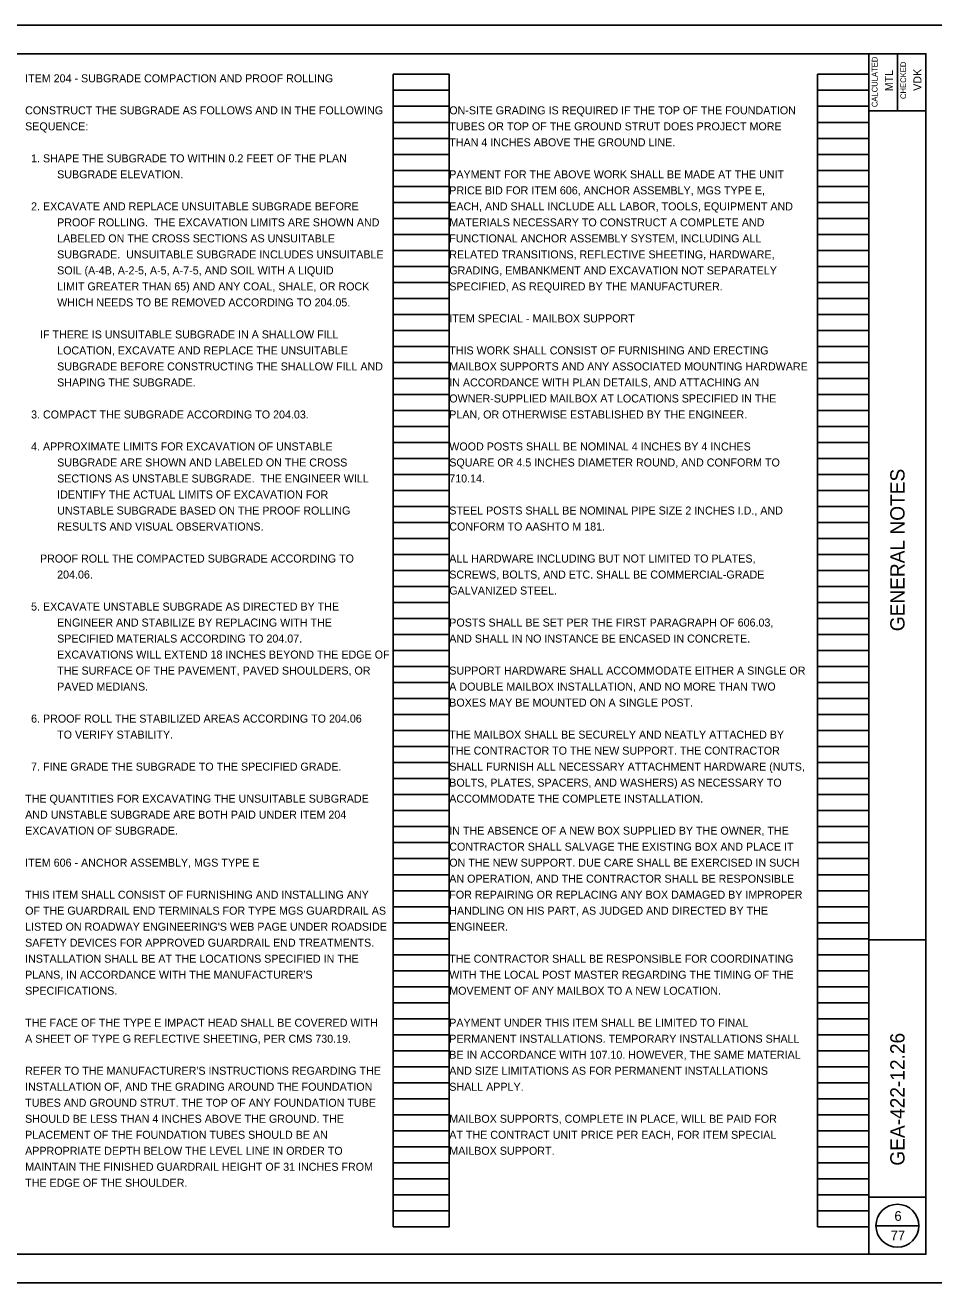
# Model space of a CAD drawing. Extents: x 0 to 41.8, y 0 to 22.
# Drawn here: x 17.74 to 33.64, y 0 to 22 of the extents above; entities that cross this region are included whole.
import ezdxf

# ---------------------------------------------------------------- set-up
doc = ezdxf.new("R2010")
doc.units = 0
for name, color, linetype in [('SC_Scratch1', 7, 'Continuous'), ('SH_Border', 7, 'Continuous'), ('SH_Cut_Line', 7, 'Continuous'), ('SH_Data', 7, 'Continuous'), ('SH_Text', 7, 'Continuous')]:
    doc.layers.add(name, color=color, linetype=linetype)

msp = doc.modelspace()

# ---------------------------------------------------------------- linework, layer by layer
at = {"layer": 'SC_Scratch1'}
for p, q in [((24.18, 0.98), (24.18, 21.14)), ((24.18, 21.14), (25.16, 21.14)), ((25.16, 0.98), (25.16, 21.14)), ((31.6, 0.98), (31.6, 21.14)), ((31.6, 21.14), (32.5, 21.14)), ((32.5, 0.98), (32.5, 21.14)), ((24.18, 20.86), (25.16, 20.86)), ((31.6, 20.86), (32.5, 20.86)), ((24.18, 20.58), (25.16, 20.58)), ((31.6, 20.58), (32.5, 20.58)), ((24.18, 20.3), (25.16, 20.3)), ((31.6, 20.3), (32.5, 20.3)), ((24.18, 20.02), (25.16, 20.02)), ((31.6, 20.02), (32.5, 20.02)), ((24.18, 19.74), (25.16, 19.74)), ((31.6, 19.74), (32.5, 19.74)), ((24.18, 19.46), (25.16, 19.46)), ((31.6, 19.46), (32.5, 19.46)), ((24.18, 19.18), (25.16, 19.18)), ((31.6, 19.18), (32.5, 19.18)), ((24.18, 18.9), (25.16, 18.9)), ((31.6, 18.9), (32.5, 18.9)), ((24.18, 18.62), (25.16, 18.62)), ((31.6, 18.62), (32.5, 18.62)), ((24.18, 18.34), (25.16, 18.34)), ((31.6, 18.34), (32.5, 18.34)), ((24.18, 18.06), (25.16, 18.06)), ((31.6, 18.06), (32.5, 18.06)), ((24.18, 17.78), (25.16, 17.78)), ((31.6, 17.78), (32.5, 17.78)), ((24.18, 17.5), (25.16, 17.5)), ((31.6, 17.5), (32.5, 17.5)), ((24.18, 17.22), (25.16, 17.22)), ((31.6, 17.22), (32.5, 17.22)), ((24.18, 16.94), (25.16, 16.94)), ((31.6, 16.94), (32.5, 16.94)), ((24.18, 16.66), (25.16, 16.66)), ((31.6, 16.66), (32.5, 16.66)), ((24.18, 16.38), (25.16, 16.38)), ((31.6, 16.38), (32.5, 16.38)), ((24.18, 16.1), (25.16, 16.1)), ((31.6, 16.1), (32.5, 16.1)), ((24.18, 15.82), (25.16, 15.82)), ((31.6, 15.82), (32.5, 15.82)), ((24.18, 15.54), (25.16, 15.54)), ((31.6, 15.54), (32.5, 15.54)), ((24.18, 15.26), (25.16, 15.26)), ((31.6, 15.26), (32.5, 15.26)), ((24.18, 14.98), (25.16, 14.98)), ((31.6, 14.98), (32.5, 14.98)), ((24.18, 14.7), (25.16, 14.7)), ((31.6, 14.7), (32.5, 14.7)), ((24.18, 14.42), (25.16, 14.42)), ((31.6, 14.42), (32.5, 14.42)), ((24.18, 14.14), (25.16, 14.14)), ((31.6, 14.14), (32.5, 14.14)), ((24.18, 13.86), (25.16, 13.86)), ((31.6, 13.86), (32.5, 13.86)), ((24.18, 13.58), (25.16, 13.58)), ((31.6, 13.58), (32.5, 13.58)), ((24.18, 13.3), (25.16, 13.3)), ((31.6, 13.3), (32.5, 13.3)), ((24.18, 13.02), (25.16, 13.02)), ((31.6, 13.02), (32.5, 13.02)), ((24.18, 12.74), (25.16, 12.74)), ((31.6, 12.74), (32.5, 12.74)), ((24.18, 12.46), (25.16, 12.46)), ((31.6, 12.46), (32.5, 12.46)), ((24.18, 12.18), (25.16, 12.18)), ((31.6, 12.18), (32.5, 12.18)), ((24.18, 11.9), (25.16, 11.9)), ((31.6, 11.9), (32.5, 11.9)), ((24.18, 11.62), (25.16, 11.62)), ((31.6, 11.62), (32.5, 11.62)), ((24.18, 11.34), (25.16, 11.34)), ((31.6, 11.34), (32.5, 11.34)), ((24.18, 11.06), (25.16, 11.06)), ((31.6, 11.06), (32.5, 11.06)), ((24.18, 10.78), (25.16, 10.78)), ((31.6, 10.78), (32.5, 10.78)), ((24.18, 10.5), (25.16, 10.5)), ((31.6, 10.5), (32.5, 10.5)), ((24.18, 10.22), (25.16, 10.22)), ((31.6, 10.22), (32.5, 10.22)), ((24.18, 9.94), (25.16, 9.94)), ((31.6, 9.94), (32.5, 9.94)), ((24.18, 9.66), (25.16, 9.66)), ((31.6, 9.66), (32.5, 9.66)), ((24.18, 9.38), (25.16, 9.38)), ((31.6, 9.38), (32.5, 9.38)), ((24.18, 9.1), (25.16, 9.1)), ((31.6, 9.1), (32.5, 9.1)), ((24.18, 8.82), (25.16, 8.82)), ((31.6, 8.82), (32.5, 8.82)), ((24.18, 8.54), (25.16, 8.54)), ((31.6, 8.54), (32.5, 8.54)), ((24.18, 8.26), (25.16, 8.26)), ((31.6, 8.26), (32.5, 8.26)), ((24.18, 7.98), (25.16, 7.98)), ((31.6, 7.98), (32.5, 7.98)), ((24.18, 7.7), (25.16, 7.7)), ((31.6, 7.7), (32.5, 7.7)), ((24.18, 7.42), (25.16, 7.42)), ((31.6, 7.42), (32.5, 7.42)), ((24.18, 7.14), (25.16, 7.14)), ((31.6, 7.14), (32.5, 7.14)), ((24.18, 6.86), (25.16, 6.86)), ((31.6, 6.86), (32.5, 6.86)), ((24.18, 6.58), (25.16, 6.58)), ((31.6, 6.58), (32.5, 6.58)), ((24.18, 6.3), (25.16, 6.3)), ((31.6, 6.3), (32.5, 6.3)), ((24.18, 6.02), (25.16, 6.02)), ((31.6, 6.02), (32.5, 6.02)), ((24.18, 5.74), (25.16, 5.74)), ((31.6, 5.74), (32.5, 5.74)), ((24.18, 5.46), (25.16, 5.46)), ((31.6, 5.46), (32.5, 5.46)), ((24.18, 5.18), (25.16, 5.18)), ((31.6, 5.18), (32.5, 5.18)), ((24.18, 4.9), (25.16, 4.9)), ((31.6, 4.9), (32.5, 4.9)), ((24.18, 4.62), (25.16, 4.62)), ((31.6, 4.62), (32.5, 4.62)), ((24.18, 4.34), (25.16, 4.34)), ((31.6, 4.34), (32.5, 4.34)), ((24.18, 4.06), (25.16, 4.06)), ((31.6, 4.06), (32.5, 4.06)), ((24.18, 3.78), (25.16, 3.78)), ((31.6, 3.78), (32.5, 3.78)), ((24.18, 3.5), (25.16, 3.5)), ((31.6, 3.5), (32.5, 3.5)), ((24.18, 3.22), (25.16, 3.22)), ((31.6, 3.22), (32.5, 3.22)), ((24.18, 2.94), (25.16, 2.94)), ((31.6, 2.94), (32.5, 2.94)), ((24.18, 2.66), (25.16, 2.66)), ((31.6, 2.66), (32.5, 2.66)), ((24.18, 2.38), (25.16, 2.38)), ((31.6, 2.38), (32.5, 2.38)), ((24.18, 2.1), (25.16, 2.1)), ((31.6, 2.1), (32.5, 2.1)), ((24.18, 1.82), (25.16, 1.82)), ((31.6, 1.82), (32.5, 1.82)), ((24.18, 1.54), (25.16, 1.54)), ((31.6, 1.54), (32.5, 1.54)), ((24.18, 1.26), (25.16, 1.26)), ((31.6, 1.26), (32.5, 1.26)), ((24.18, 0.98), (25.16, 0.98)), ((31.6, 0.98), (32.5, 0.98))]:
    msp.add_line(p, q, dxfattribs=at)
at = {"layer": 'SH_Border'}
for p, q in [((32.5, 0.5), (32.5, 21.5)), ((33, 21.5), (33, 20.5)), ((32.5, 20.5), (33.5, 20.5)), ((32.5, 6), (33.5, 6)), ((32.5, 1.5), (33.5, 1.5))]:
    msp.add_line(p, q, dxfattribs=at)
msp.add_lwpolyline([(2, 21.5), (33.5, 21.5), (33.5, 0.5), (2, 0.5)], close=True, dxfattribs=at)
at = {"layer": 'SH_Cut_Line'}
msp.add_lwpolyline([(0, 0), (34, 0), (34, 22), (0, 22)], close=True, dxfattribs=at)
at = {"layer": 'SH_Data'}
msp.add_line((32.625, 1), (33.375, 1), dxfattribs=at)
msp.add_circle((33, 1), 0.375, dxfattribs=at)

# ---------------------------------------------------------------- texts
for s, height, p in [('CALCULATED', 0.1, (32.652, 20.565)), ('CHECKED', 0.1, (33.152, 20.708)), ('MTL', 0.14, (32.92, 20.844)), ('VDK', 0.14, (33.42, 20.851)), ('GENERAL NOTES', 0.25, (33.125, 11.398)), (' GEA-422-12.26 ', 0.25, (33.125, 1.957))]:
    msp.add_text(s, height=height, rotation=90, dxfattribs=at).set_placement(p)
for s, p in [('6', (32.948, 1.085)), ('77', (32.882, 0.745))]:
    msp.add_text(s, height=0.17, dxfattribs=at).set_placement(p)
at = {"layer": 'SH_Text'}
for s, p in [('ITEM 204 - SUBGRADE COMPACTION AND PROOF ROLLING', (17.74, 21)), ('CONSTRUCT THE SUBGRADE AS FOLLOWS AND IN THE FOLLOWING ', (17.74, 20.44)), ('ON-SITE GRADING IS REQUIRED IF THE TOP OF THE FOUNDATION ', (25.16, 20.44)), ('SEQUENCE:', (17.74, 20.16)), ('TUBES OR TOP OF THE GROUND STRUT DOES PROJECT MORE ', (25.16, 20.16)), ('THAN 4 INCHES ABOVE THE GROUND LINE.', (25.16, 19.88)), ('  1. SHAPE THE SUBGRADE TO WITHIN 0.2 FEET OF THE PLAN ', (17.74, 19.6)), ('SUBGRADE ELEVATION.', (18.3, 19.32)), ('PAYMENT FOR THE ABOVE WORK SHALL BE MADE AT THE UNIT ', (25.16, 19.32)), ('PRICE BID FOR ITEM 606, ANCHOR ASSEMBLY, MGS TYPE E, ', (25.16, 19.04)), ('  2. EXCAVATE AND REPLACE UNSUITABLE SUBGRADE BEFORE ', (17.74, 18.76)), ('EACH, AND SHALL INCLUDE ALL LABOR, TOOLS, EQUIPMENT AND ', (25.16, 18.76)), ('PROOF ROLLING.  THE EXCAVATION LIMITS ARE SHOWN AND ', (18.3, 18.48)), ('MATERIALS NECESSARY TO CONSTRUCT A COMPLETE AND ', (25.16, 18.48)), ('LABELED ON THE CROSS SECTIONS AS UNSUITABLE ', (18.3, 18.2)), ('FUNCTIONAL ANCHOR ASSEMBLY SYSTEM, INCLUDING ALL ', (25.16, 18.2)), ('SUBGRADE.  UNSUITABLE SUBGRADE INCLUDES UNSUITABLE ', (18.3, 17.92)), ('RELATED TRANSITIONS, REFLECTIVE SHEETING, HARDWARE, ', (25.16, 17.92)), ('SOIL (A-4B, A-2-5, A-5, A-7-5, AND SOIL WITH A LIQUID ', (18.3, 17.64)), ('GRADING, EMBANKMENT AND EXCAVATION NOT SEPARATELY ', (25.16, 17.64)), ('LIMIT GREATER THAN 65) AND ANY COAL, SHALE, OR ROCK ', (18.3, 17.36)), ('SPECIFIED, AS REQUIRED BY THE MANUFACTURER.', (25.16, 17.36)), ('WHICH NEEDS TO BE REMOVED ACCORDING TO 204.05.', (18.3, 17.08)), ('ITEM SPECIAL - MAILBOX SUPPORT', (25.16, 16.8)), ('     IF THERE IS UNSUITABLE SUBGRADE IN A SHALLOW FILL ', (17.74, 16.52)), ('LOCATION, EXCAVATE AND REPLACE THE UNSUITABLE ', (18.3, 16.24)), ('THIS WORK SHALL CONSIST OF FURNISHING AND ERECTING ', (25.16, 16.24)), ('SUBGRADE BEFORE CONSTRUCTING THE SHALLOW FILL AND ', (18.3, 15.96)), ('MAILBOX SUPPORTS AND ANY ASSOCIATED MOUNTING HARDWARE ', (25.16, 15.96)), ('SHAPING THE SUBGRADE.', (18.3, 15.68)), ('IN ACCORDANCE WITH PLAN DETAILS, AND ATTACHING AN ', (25.16, 15.68)), ('OWNER-SUPPLIED MAILBOX AT LOCATIONS SPECIFIED IN THE ', (25.16, 15.4)), ('  3. COMPACT THE SUBGRADE ACCORDING TO 204.03.', (17.74, 15.12)), ('PLAN, OR OTHERWISE ESTABLISHED BY THE ENGINEER.', (25.16, 15.12)), ('  4. APPROXIMATE LIMITS FOR EXCAVATION OF UNSTABLE ', (17.74, 14.56)), ('WOOD POSTS SHALL BE NOMINAL 4 INCHES BY 4 INCHES ', (25.16, 14.56)), ('SUBGRADE ARE SHOWN AND LABELED ON THE CROSS ', (18.3, 14.28)), ('SQUARE OR 4.5 INCHES DIAMETER ROUND, AND CONFORM TO ', (25.16, 14.28)), ('SECTIONS AS UNSTABLE SUBGRADE.  THE ENGINEER WILL ', (18.3, 14)), ('710.14.', (25.16, 14)), ('IDENTIFY THE ACTUAL LIMITS OF EXCAVATION FOR ', (18.3, 13.72)), ('UNSTABLE SUBGRADE BASED ON THE PROOF ROLLING ', (18.3, 13.44)), ('STEEL POSTS SHALL BE NOMINAL PIPE SIZE 2 INCHES I.D., AND ', (25.16, 13.44)), ('RESULTS AND VISUAL OBSERVATIONS.', (18.3, 13.16)), ('CONFORM TO AASHTO M 181.', (25.16, 13.16)), ('     PROOF ROLL THE COMPACTED SUBGRADE ACCORDING TO ', (17.74, 12.6)), ('ALL HARDWARE INCLUDING BUT NOT LIMITED TO PLATES, ', (25.16, 12.6)), ('204.06.', (18.3, 12.32)), ('SCREWS, BOLTS, AND ETC. SHALL BE COMMERCIAL-GRADE ', (25.16, 12.32)), ('GALVANIZED STEEL.', (25.16, 12.04)), ('  5. EXCAVATE UNSTABLE SUBGRADE AS DIRECTED BY THE ', (17.74, 11.76)), ('ENGINEER AND STABILIZE BY REPLACING WITH THE ', (18.3, 11.48)), ('POSTS SHALL BE SET PER THE FIRST PARAGRAPH OF 606.03, ', (25.16, 11.48)), ('SPECIFIED MATERIALS ACCORDING TO 204.07.  ', (18.3, 11.2)), ('AND SHALL IN NO INSTANCE BE ENCASED IN CONCRETE.', (25.16, 11.2)), ('EXCAVATIONS WILL EXTEND 18 INCHES BEYOND THE EDGE OF ', (18.3, 10.92)), ('THE SURFACE OF THE PAVEMENT, PAVED SHOULDERS, OR ', (18.3, 10.64)), ('SUPPORT HARDWARE SHALL ACCOMMODATE EITHER A SINGLE OR ', (25.16, 10.64)), ('PAVED MEDIANS.', (18.3, 10.36)), ('A DOUBLE MAILBOX INSTALLATION, AND NO MORE THAN TWO ', (25.16, 10.36)), ('BOXES MAY BE MOUNTED ON A SINGLE POST.', (25.16, 10.08)), ('  6. PROOF ROLL THE STABILIZED AREAS ACCORDING TO 204.06 ', (17.74, 9.8)), ('TO VERIFY STABILITY.', (18.3, 9.52)), ('THE MAILBOX SHALL BE SECURELY AND NEATLY ATTACHED BY ', (25.16, 9.52)), ('THE CONTRACTOR TO THE NEW SUPPORT. THE CONTRACTOR ', (25.16, 9.24)), ('  7. FINE GRADE THE SUBGRADE TO THE SPECIFIED GRADE.', (17.74, 8.96)), ('SHALL FURNISH ALL NECESSARY ATTACHMENT HARDWARE (NUTS, ', (25.16, 8.96)), ('BOLTS, PLATES, SPACERS, AND WASHERS) AS NECESSARY TO ', (25.16, 8.68)), ('THE QUANTITIES FOR EXCAVATING THE UNSUITABLE SUBGRADE ', (17.74, 8.4)), ('ACCOMMODATE THE COMPLETE INSTALLATION.', (25.16, 8.4)), ('AND UNSTABLE SUBGRADE ARE BOTH PAID UNDER ITEM 204 ', (17.74, 8.12)), ('EXCAVATION OF SUBGRADE.', (17.74, 7.84)), ('IN THE ABSENCE OF A NEW BOX SUPPLIED BY THE OWNER, THE ', (25.16, 7.84)), ('CONTRACTOR SHALL SALVAGE THE EXISTING BOX AND PLACE IT ', (25.16, 7.56)), ('ITEM 606 - ANCHOR ASSEMBLY, MGS TYPE E', (17.74, 7.28)), ('ON THE NEW SUPPORT. DUE CARE SHALL BE EXERCISED IN SUCH ', (25.16, 7.28)), ('AN OPERATION, AND THE CONTRACTOR SHALL BE RESPONSIBLE ', (25.16, 7)), ('THIS ITEM SHALL CONSIST OF FURNISHING AND INSTALLING ANY ', (17.74, 6.72)), ('FOR REPAIRING OR REPLACING ANY BOX DAMAGED BY IMPROPER ', (25.16, 6.72)), ('OF THE GUARDRAIL END TERMINALS FOR TYPE MGS GUARDRAIL AS ', (17.74, 6.44)), ('HANDLING ON HIS PART, AS JUDGED AND DIRECTED BY THE ', (25.16, 6.44)), ("LISTED ON ROADWAY ENGINEERING'S WEB PAGE UNDER ROADSIDE ", (17.74, 6.16)), ('ENGINEER.', (25.16, 6.16)), ('SAFETY DEVICES FOR APPROVED GUARDRAIL END TREATMENTS. ', (17.74, 5.88)), ('INSTALLATION SHALL BE AT THE LOCATIONS SPECIFIED IN THE ', (17.74, 5.6)), ('THE CONTRACTOR SHALL BE RESPONSIBLE FOR COORDINATING ', (25.16, 5.6)), ("PLANS, IN ACCORDANCE WITH THE MANUFACTURER'S ", (17.74, 5.32)), ('WITH THE LOCAL POST MASTER REGARDING THE TIMING OF THE ', (25.16, 5.32)), ('SPECIFICATIONS.', (17.74, 5.04)), ('MOVEMENT OF ANY MAILBOX TO A NEW LOCATION.', (25.16, 5.04)), ('THE FACE OF THE TYPE E IMPACT HEAD SHALL BE COVERED WITH ', (17.74, 4.48)), ('PAYMENT UNDER THIS ITEM SHALL BE LIMITED TO FINAL ', (25.16, 4.48)), ('A SHEET OF TYPE G REFLECTIVE SHEETING, PER CMS 730.19.', (17.74, 4.2)), ('PERMANENT INSTALLATIONS. TEMPORARY INSTALLATIONS SHALL ', (25.16, 4.2)), ('BE IN ACCORDANCE WITH 107.10. HOWEVER, THE SAME MATERIAL ', (25.16, 3.92)), ("REFER TO THE MANUFACTURER'S INSTRUCTIONS REGARDING THE ", (17.74, 3.64)), ('AND SIZE LIMITATIONS AS FOR PERMANENT INSTALLATIONS ', (25.16, 3.64)), ('INSTALLATION OF, AND THE GRADING AROUND THE FOUNDATION ', (17.74, 3.36)), ('SHALL APPLY.', (25.16, 3.36)), ('TUBES AND GROUND STRUT. THE TOP OF ANY FOUNDATION TUBE ', (17.74, 3.08)), ('SHOULD BE LESS THAN 4 INCHES ABOVE THE GROUND. THE ', (17.74, 2.8)), ('MAILBOX SUPPORTS, COMPLETE IN PLACE, WILL BE PAID FOR ', (25.16, 2.8)), ('PLACEMENT OF THE FOUNDATION TUBES SHOULD BE AN ', (17.74, 2.52)), ('AT THE CONTRACT UNIT PRICE PER EACH, FOR ITEM SPECIAL ', (25.16, 2.52)), ('APPROPRIATE DEPTH BELOW THE LEVEL LINE IN ORDER TO ', (17.74, 2.24)), ('MAILBOX SUPPORT.', (25.16, 2.24)), ('MAINTAIN THE FINISHED GUARDRAIL HEIGHT OF 31 INCHES FROM ', (17.74, 1.96)), ('THE EDGE OF THE SHOULDER.', (17.74, 1.68))]:
    msp.add_text(s, height=0.14, dxfattribs=at).set_placement(p)

doc.saveas('drawing.dxf')
